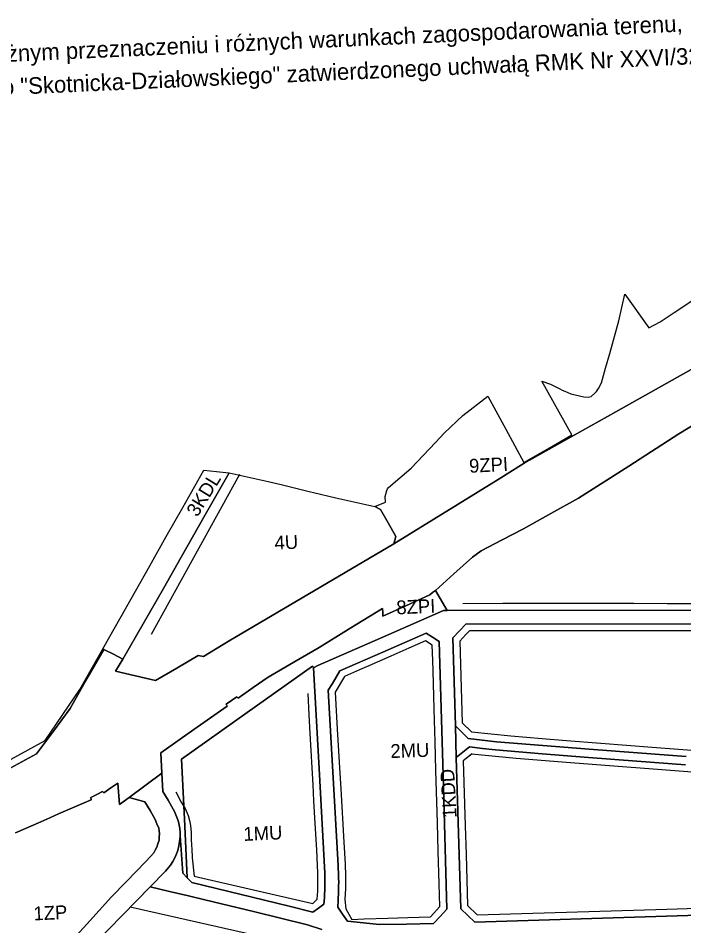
# Model space of a CAD drawing. Extents: x 7418021 to 7419743, y 5540231 to 5541685.
# Drawn here: x 7418764 to 7419247, y 5541026 to 5541685 of the extents above; entities that cross this region are included whole.
import ezdxf

# ---------------------------------------------------------------- set-up
doc = ezdxf.new("R2010")
doc.units = 0
for name, color, linetype in [('info', 7, 'Continuous'), ('linie_rozgraniczajace', 7, 'Continuous'), ('linie_zabudowy_nieprzekraczalne', 7, 'Continuous'), ('oznaczenia_przeznaczen', 7, 'Continuous')]:
    doc.layers.add(name, color=color, linetype=linetype)

msp = doc.modelspace()

# ---------------------------------------------------------------- linework, layer by layer
at = {"layer": 'linie_rozgraniczajace'}
for points in [[(7419264.06, 5541436.17), (7419197.72, 5541398.92), (7419131.37, 5541361.67), (7419131.05, 5541362.12), (7419148.44, 5541372.18), (7419165.84, 5541382.25), (7419144.09, 5541421.08), (7419150.41, 5541418.88), (7419157.19, 5541415.49), (7419158.97, 5541414.65), (7419160.74, 5541413.8), (7419165.14, 5541412.08), (7419174.5, 5541409.72), (7419177.8, 5541409.47), (7419180.02, 5541409.94), (7419182.83, 5541412.7), (7419183.74, 5541413.6), (7419185.3, 5541415.8), (7419187.43, 5541419.95), (7419190.41, 5541430.57), (7419193.39, 5541441.19), (7419199.93, 5541464.97), (7419204.41, 5541484.28), (7419221.63, 5541459.9), (7419229.97, 5541464.16), (7419240, 5541470.9), (7419241.95, 5541472.21), (7419268.64, 5541490.14)], [(7418742.75, 5541131.91), (7418777.69, 5541150.66), (7418789.83, 5541167.12), (7418801.97, 5541183.59), (7418814.18, 5541205.07), (7418826.39, 5541226.55), (7418833.35, 5541222.96), (7418840.31, 5541219.37), (7418834.89, 5541210.65), (7418849.45, 5541207.26), (7418864.02, 5541203.87), (7418879.49, 5541213.02), (7418894.95, 5541222.16), (7418898.76, 5541221.27), (7418917.39, 5541232.64), (7419036.88, 5541303.16), (7419112.45, 5541349.78), (7419131.37, 5541361.67), (7419197.72, 5541398.92), (7419264.06, 5541436.17)], [(7419305.93, 5541420.97), (7419243.56, 5541382.86), (7419207.12, 5541359.52), (7419170.68, 5541336.19), (7419150.78, 5541325.05), (7419130.88, 5541313.92), (7419115.45, 5541305.98), (7419100.02, 5541298.04), (7419093.87, 5541293.42), (7419080.42, 5541281.38), (7419066.97, 5541269.34), (7419064.9, 5541267.73), (7419062.83, 5541266.12), (7419045.87, 5541258.36), (7419028.91, 5541250.61), (7419028.69, 5541253.4)], [(7419298.53, 5541254.95), (7419075.49, 5541254.87), (7419066.97, 5541269.34), (7419080.42, 5541281.38), (7419093.87, 5541293.42), (7419100.02, 5541298.04), (7419115.45, 5541305.98), (7419130.88, 5541313.92), (7419150.78, 5541325.05), (7419170.68, 5541336.19), (7419207.12, 5541359.52), (7419243.56, 5541382.86), (7419305.93, 5541420.97)], [(7419028.69, 5541253.4), (7419028.48, 5541256.19), (7419005.52, 5541242.1), (7418982.57, 5541228), (7418964.15, 5541217.25), (7418945.74, 5541206.49), (7418934.77, 5541198.83), (7418923.8, 5541191.17), (7418923.34, 5541191.68), (7418922.89, 5541192.2), (7418918.99, 5541189.47), (7418915.08, 5541186.75), (7418916, 5541185.36), (7418891.84, 5541168.43), (7418867.68, 5541151.49), (7418868.53, 5541136.69), (7418844.8, 5541119.15), (7418837.76, 5541113.94), (7418836.72, 5541129.55), (7418831.57, 5541126.04), (7418826.43, 5541122.53), (7418825.48, 5541123.51), (7418821.25, 5541121.25), (7418817.02, 5541119), (7418817.29, 5541117.38), (7418805.4, 5541112.33), (7418793.51, 5541107.27), (7418787.18, 5541104.33), (7418780.85, 5541101.4), (7418762.43, 5541093.5)], [(7418883.64, 5541064.17), (7418886.94, 5541060.75), (7418890.24, 5541057.32), (7418960.86, 5541040.15), (7418978.13, 5541035.89), (7418982.1, 5541038.8), (7418986.08, 5541041.71), (7418986.41, 5541046.14), (7418986.58, 5541049.33), (7418986.64, 5541050.96), (7418986.75, 5541054.72), (7418986.79, 5541057.9), (7418986.77, 5541060.93), (7418986.7, 5541064.21), (7418982.59, 5541140.19), (7418978.58, 5541213.14), (7418981.57, 5541214.72), (7419027.22, 5541234.79), (7419072.87, 5541254.85), (7419075.49, 5541254.87), (7419298.53, 5541254.95)], [(7419295.55, 5541244.94), (7419089.24, 5541244.96), (7419084.38, 5541239.95), (7419079.53, 5541234.94), (7419081.4, 5541171.04), (7419082.07, 5541148.05), (7419085.29, 5541038.29), (7419090.43, 5541033.48), (7419095.57, 5541028.67), (7419234.58, 5541032.97), (7419373.59, 5541037.27)], [(7419248.73, 5541148.79), (7419213.55, 5541151.46), (7419178.38, 5541154.14), (7419144.78, 5541156.83), (7419111.18, 5541159.53), (7419100.94, 5541160.69), (7419090.71, 5541161.86), (7419081.4, 5541171.04), (7419079.53, 5541234.94), (7419084.38, 5541239.95), (7419089.24, 5541244.96), (7419295.55, 5541244.94)], [(7419248.28, 5541142.8), (7419213.1, 5541145.48), (7419177.92, 5541148.15), (7419144.26, 5541150.85), (7419110.6, 5541153.55), (7419101.15, 5541154.63), (7419091.71, 5541155.7), (7419086.89, 5541151.88), (7419082.07, 5541148.05), (7419081.4, 5541171.04), (7419090.71, 5541161.86), (7419100.94, 5541160.69), (7419111.18, 5541159.53), (7419144.78, 5541156.83), (7419178.38, 5541154.14), (7419213.55, 5541151.46), (7419248.73, 5541148.79)], [(7419373.59, 5541037.27), (7419234.58, 5541032.97), (7419095.57, 5541028.67), (7419090.43, 5541033.48), (7419085.29, 5541038.29), (7419082.07, 5541148.05), (7419086.89, 5541151.88), (7419091.71, 5541155.7), (7419101.15, 5541154.63), (7419110.6, 5541153.55), (7419144.26, 5541150.85), (7419177.92, 5541148.15), (7419213.1, 5541145.48), (7419248.28, 5541142.8)], [(7418796.31, 5541007.56), (7418814.14, 5541027.22), (7418831.98, 5541046.89), (7418842.72, 5541057.93), (7418856.93, 5541072.55), (7418860.41, 5541076.13), (7418862.63, 5541078.85), (7418863.79, 5541080.89), (7418864.94, 5541082.93), (7418865.7, 5541085.53), (7418866.46, 5541088.14), (7418866.6, 5541090.46), (7418866.75, 5541092.78), (7418866.49, 5541094.75), (7418866.24, 5541096.71), (7418864.99, 5541099.89), (7418863.75, 5541103.08), (7418860.02, 5541109.52), (7418856.29, 5541115.97), (7418844.8, 5541119.15), (7418868.53, 5541136.69)], [(7418868.53, 5541136.69), (7418869.27, 5541123.48), (7418873, 5541117.04), (7418876.73, 5541110.59), (7418877.71, 5541108.79), (7418878.23, 5541107.67), (7418878.76, 5541106.55), (7418879.71, 5541104.09), (7418880.12, 5541102.76), (7418880.52, 5541101.43), (7418880.81, 5541100.19), (7418881.29, 5541097.71), (7418881.49, 5541096.47), (7418881.74, 5541093.53), (7418881.7, 5541091.2), (7418881.66, 5541088.87), (7418880.89, 5541083.96), (7418880.05, 5541080.63), (7418879.17, 5541078.13), (7418878.72, 5541076.99), (7418877.66, 5541074.72), (7418876.43, 5541072.52), (7418874.69, 5541069.87), (7418871.17, 5541065.67), (7418860.04, 5541054.22), (7418820.04, 5541013.07)], [(7418762.43, 5541093.5), (7418780.85, 5541101.4), (7418787.18, 5541104.33), (7418793.51, 5541107.27), (7418805.4, 5541112.33), (7418817.29, 5541117.38), (7418817.02, 5541119), (7418821.25, 5541121.25), (7418825.48, 5541123.51), (7418826.43, 5541122.53), (7418831.57, 5541126.04), (7418836.72, 5541129.55), (7418837.76, 5541113.94), (7418844.8, 5541119.15), (7418856.29, 5541115.97), (7418860.02, 5541109.52), (7418863.75, 5541103.08), (7418864.99, 5541099.89), (7418866.24, 5541096.71), (7418866.49, 5541094.75), (7418866.75, 5541092.78), (7418866.6, 5541090.46), (7418866.46, 5541088.14), (7418865.7, 5541085.53), (7418864.94, 5541082.93), (7418863.79, 5541080.89), (7418862.63, 5541078.85), (7418860.41, 5541076.13), (7418856.93, 5541072.55), (7418842.72, 5541057.93), (7418831.98, 5541046.89), (7418814.14, 5541027.22), (7418796.31, 5541007.56)], [(7418984.55, 5541023.35), (7418974.12, 5541026.58), (7418935.01, 5541036.21), (7418899.75, 5541044.79), (7418887.93, 5541047.59), (7418873.98, 5541050.9), (7418860.04, 5541054.22), (7418871.17, 5541065.67), (7418874.69, 5541069.87), (7418876.43, 5541072.52), (7418877.66, 5541074.72), (7418878.72, 5541076.99), (7418879.17, 5541078.13), (7418880.05, 5541080.63), (7418880.89, 5541083.96), (7418881.66, 5541088.87), (7418881.7, 5541091.2), (7418882.67, 5541077.69), (7418883.64, 5541064.17)], [(7418820.04, 5541013.07), (7418860.04, 5541054.22), (7418873.98, 5541050.9), (7418887.93, 5541047.59), (7418899.75, 5541044.79), (7418935.01, 5541036.21), (7418974.12, 5541026.58), (7418984.55, 5541023.35)]]:
    msp.add_lwpolyline(points, dxfattribs=at)
for points in [[(7419032.28, 5541342.94), (7419032.82, 5541344.03), (7419041.06, 5541351.03), (7419049.3, 5541358.04), (7419058.15, 5541367.33), (7419067, 5541376.61), (7419073.63, 5541383.76), (7419086.75, 5541396.36), (7419105.07, 5541410.34), (7419118.06, 5541386.23), (7419131.05, 5541362.12), (7419131.37, 5541361.67), (7419112.45, 5541349.78), (7419036.88, 5541303.16), (7419036.9, 5541303.24), (7419038.24, 5541308.51), (7419032.63, 5541318.27), (7419027.03, 5541328.04), (7419022.91, 5541330.31), (7419030.73, 5541333.29), (7419030.49, 5541337.45), (7419031.74, 5541341.84)], [(7418838.98, 5541250.29), (7418859.7, 5541287.19), (7418871.7, 5541308.37), (7418883.77, 5541329.49), (7418899.07, 5541356.65), (7418908.09, 5541355.71), (7418917.11, 5541354.76), (7418917.38, 5541354.7), (7418899.86, 5541324.08), (7418882.62, 5541293.4), (7418869.84, 5541270.72), (7418840.31, 5541219.37), (7418833.35, 5541222.96), (7418826.39, 5541226.55), (7418825.81, 5541226.83)], [(7418864.02, 5541203.87), (7418849.45, 5541207.26), (7418834.89, 5541210.65), (7418840.31, 5541219.37), (7418869.84, 5541270.72), (7418882.62, 5541293.4), (7418899.86, 5541324.08), (7418917.38, 5541354.7), (7418945.56, 5541348.36), (7418954.98, 5541346.24), (7418976.25, 5541340.91), (7418978.41, 5541340.37), (7418994.78, 5541336.41), (7419022.91, 5541330.31), (7419027.03, 5541328.04), (7419032.63, 5541318.27), (7419038.24, 5541308.51), (7419036.9, 5541303.24), (7419036.88, 5541303.16), (7418917.39, 5541232.64), (7418898.76, 5541221.27), (7418894.95, 5541222.16), (7418879.49, 5541213.02)], [(7419066.97, 5541269.34), (7419075.49, 5541254.87), (7419072.87, 5541254.85), (7419027.22, 5541234.79), (7418981.57, 5541214.72), (7418978.58, 5541213.14), (7418978.23, 5541213.76), (7418977.89, 5541214.36), (7418930.31, 5541180.62), (7418882.73, 5541146.87), (7418884.97, 5541103.67), (7418886.94, 5541060.75), (7418883.64, 5541064.17), (7418882.67, 5541077.69), (7418881.7, 5541091.2), (7418881.74, 5541093.53), (7418881.49, 5541096.47), (7418881.29, 5541097.71), (7418880.81, 5541100.19), (7418880.52, 5541101.43), (7418880.12, 5541102.76), (7418879.71, 5541104.09), (7418878.76, 5541106.55), (7418878.23, 5541107.67), (7418877.71, 5541108.79), (7418876.73, 5541110.59), (7418873, 5541117.04), (7418869.27, 5541123.48), (7418868.53, 5541136.69), (7418867.68, 5541151.49), (7418891.84, 5541168.43), (7418916, 5541185.36), (7418915.08, 5541186.75), (7418918.99, 5541189.47), (7418922.89, 5541192.2), (7418923.34, 5541191.68), (7418923.8, 5541191.17), (7418934.77, 5541198.83), (7418945.74, 5541206.49), (7418964.15, 5541217.25), (7418982.57, 5541228), (7419005.52, 5541242.1), (7419028.48, 5541256.19), (7419028.69, 5541253.4), (7419028.91, 5541250.61), (7419045.87, 5541258.36), (7419062.83, 5541266.12), (7419064.9, 5541267.73)], [(7419069.6, 5541232.37), (7419064.88, 5541235.35), (7419060.15, 5541238.34), (7419028.89, 5541224.6), (7418997.63, 5541210.85), (7418992.3, 5541201.84), (7418989.06, 5541196.85), (7418992.77, 5541133.22), (7418996.48, 5541069.6), (7418996.75, 5541062.15), (7418996.77, 5541060.02), (7418996.79, 5541057.89), (7418996.73, 5541054.77), (7418996.68, 5541051.65), (7418996.55, 5541048.96), (7418996.43, 5541046.26), (7418996.29, 5541044.27), (7418996.11, 5541039.56), (7418999.62, 5541034.48), (7419003.13, 5541029.39), (7419014.68, 5541028.14), (7419026.23, 5541026.88), (7419045.91, 5541027.22), (7419065.59, 5541027.56), (7419070.44, 5541032.74), (7419075.29, 5541037.92), (7419072.45, 5541135.14)], [(7419069.6, 5541232.37), (7419072.45, 5541135.14), (7419075.29, 5541037.92), (7419070.44, 5541032.74), (7419065.59, 5541027.56), (7419045.91, 5541027.22), (7419026.23, 5541026.88), (7419014.68, 5541028.14), (7419003.13, 5541029.39), (7418999.62, 5541034.48), (7418996.11, 5541039.56), (7418996.29, 5541044.27), (7418996.43, 5541046.26), (7418996.55, 5541048.96), (7418996.68, 5541051.65), (7418996.73, 5541054.77), (7418996.79, 5541057.89), (7418996.77, 5541060.02), (7418996.75, 5541062.15), (7418996.48, 5541069.6), (7418992.77, 5541133.22), (7418989.06, 5541196.85), (7418992.3, 5541201.84), (7418997.63, 5541210.85), (7419028.89, 5541224.6), (7419060.15, 5541238.34), (7419064.88, 5541235.35)], [(7418826.39, 5541226.55), (7418814.18, 5541205.07), (7418801.97, 5541183.59), (7418789.83, 5541167.12), (7418777.69, 5541150.66), (7418742.75, 5541131.91), (7418712.48, 5541116.29), (7418685.89, 5541102.62), (7418659.3, 5541088.95), (7418633.99, 5541078.77), (7418529.23, 5541035.2), (7418449.78, 5541001.82), (7418444.4, 5541004.3), (7418520.87, 5541036.04), (7418619.89, 5541077.13), (7418704.01, 5541117.02), (7418743.95, 5541138.74), (7418783.9, 5541160.46), (7418808.95, 5541197.4), (7418825.59, 5541226.44), (7418825.81, 5541226.83)], [(7418886.94, 5541060.75), (7418884.97, 5541103.67), (7418882.73, 5541146.87), (7418930.31, 5541180.62), (7418977.89, 5541214.36), (7418978.23, 5541213.76), (7418978.58, 5541213.14), (7418982.59, 5541140.19), (7418986.7, 5541064.21), (7418986.77, 5541060.93), (7418986.79, 5541057.9), (7418986.75, 5541054.72), (7418986.64, 5541050.96), (7418986.58, 5541049.33), (7418986.41, 5541046.14), (7418986.08, 5541041.71), (7418982.1, 5541038.8), (7418978.13, 5541035.89), (7418960.86, 5541040.15), (7418890.24, 5541057.32)]]:
    msp.add_lwpolyline(points, close=True, dxfattribs=at)
at = {"layer": 'linie_zabudowy_nieprzekraczalne'}
for points in [[(7418924.88, 5541353.49), (7418860.86, 5541237.41)], [(7419086.75, 5541259.89), (7419115.95, 5541259.97)], [(7419115.95, 5541259.97), (7419136.8, 5541259.96)], [(7419136.8, 5541259.96), (7419159.88, 5541259.96)], [(7419159.88, 5541259.96), (7419184.74, 5541259.96)], [(7419184.74, 5541259.96), (7419210.9, 5541259.96)], [(7419210.9, 5541259.96), (7419235.07, 5541259.95)], [(7419235.07, 5541259.95), (7419266.19, 5541259.95)], [(7419091.73, 5541239.96), (7419088.94, 5541237.23)], [(7419116.54, 5541239.96), (7419091.73, 5541239.96)], [(7419131.96, 5541239.95), (7419116.54, 5541239.96)], [(7419158.04, 5541239.95), (7419131.96, 5541239.95)], [(7419201.16, 5541239.95), (7419158.04, 5541239.95)], [(7419217.3, 5541239.95), (7419201.16, 5541239.95)], [(7419242.13, 5541239.95), (7419217.3, 5541239.95)], [(7419277.44, 5541239.94), (7419242.13, 5541239.95)], [(7419059.73, 5541232.69), (7419047.65, 5541227.38)], [(7419064.68, 5541229.56), (7419059.73, 5541232.69)], [(7419088.94, 5541237.23), (7419084.77, 5541232.51)], [(7419084.77, 5541232.51), (7419085.35, 5541207.02)], [(7419047.65, 5541227.38), (7419034.54, 5541221.62)], [(7419065, 5541218.56), (7419064.68, 5541229.56)], [(7419034.54, 5541221.62), (7419018.72, 5541214.67)], [(7419065.22, 5541211.05), (7419065, 5541218.56)], [(7419011.9, 5541211.67), (7419001.08, 5541206.91)], [(7419018.72, 5541214.67), (7419011.9, 5541211.67)], [(7419001.08, 5541206.91), (7418994.14, 5541195.58)], [(7419065.77, 5541192.35), (7419065.22, 5541211.05)], [(7419085.35, 5541207.02), (7419086.34, 5541173.19)], [(7418975.45, 5541179.09), (7418974.6, 5541194.55)], [(7418994.14, 5541195.58), (7418995.71, 5541168.69)], [(7419066.28, 5541174.86), (7419065.77, 5541192.35)], [(7418976.2, 5541165.49), (7418975.45, 5541179.09)], [(7419066.73, 5541159.49), (7419066.28, 5541174.86)], [(7419086.34, 5541173.19), (7419093, 5541166.63)], [(7418978.24, 5541128.28), (7418976.2, 5541165.49)], [(7418995.71, 5541168.69), (7418997.58, 5541136.61)], [(7419093, 5541166.63), (7419121.6, 5541163.71)], [(7419067.35, 5541138.53), (7419066.73, 5541159.49)], [(7419121.6, 5541163.71), (7419144.37, 5541161.88)], [(7419144.37, 5541161.88), (7419162.1, 5541160.46)], [(7419162.1, 5541160.46), (7419186.84, 5541158.51)], [(7419186.84, 5541158.51), (7419224.22, 5541155.67)], [(7419224.22, 5541155.67), (7419246.39, 5541153.98)], [(7419246.39, 5541153.98), (7419273.49, 5541151.98)], [(7419093.58, 5541150.8), (7419087.15, 5541145.7)], [(7419093.2, 5541150.5), (7419087.15, 5541145.7)], [(7419087.15, 5541145.7), (7419088.53, 5541098.52)], [(7419125.46, 5541147.35), (7419093.2, 5541150.5)], [(7419165.02, 5541144.17), (7419125.46, 5541147.35)], [(7419347.74, 5541130.08), (7419165.02, 5541144.17)], [(7418997.58, 5541136.61), (7418998.23, 5541125.45)], [(7419068.46, 5541100.64), (7419067.35, 5541138.53)], [(7418978.88, 5541116.59), (7418978.24, 5541128.28)], [(7418878.65, 5541123.25), (7418882.57, 5541115.71)], [(7418998.23, 5541125.45), (7419000.49, 5541086.69)], [(7418882.57, 5541115.71), (7418885.51, 5541111.01)], [(7418979.78, 5541100.19), (7418978.88, 5541116.59)], [(7418885.51, 5541111.01), (7418887.5, 5541105.98)], [(7418887.5, 5541105.98), (7418888.52, 5541102.37)], [(7418888.52, 5541102.37), (7418889.22, 5541098.81)], [(7418980.83, 5541081.17), (7418979.78, 5541100.19)], [(7419069.06, 5541080.02), (7419068.46, 5541100.64)], [(7418889.22, 5541098.81), (7418889.74, 5541093.65)], [(7418889.74, 5541093.65), (7418889.67, 5541089.13)], [(7419088.53, 5541098.52), (7419089.14, 5541077.64)], [(7418889.67, 5541089.13), (7418890.13, 5541084.19)], [(7419000.49, 5541086.69), (7419001.43, 5541070.64)], [(7418890.13, 5541084.19), (7418890.23, 5541081.73)], [(7418890.23, 5541081.73), (7418890.42, 5541075.17)], [(7418981.46, 5541069.66), (7418980.83, 5541081.17)], [(7419069.75, 5541056.44), (7419069.06, 5541080.02)], [(7418890.42, 5541075.17), (7418891.95, 5541062.06)], [(7419089.14, 5541077.64), (7419090.22, 5541040.79)], [(7418981.69, 5541064.42), (7418981.46, 5541069.66)], [(7419001.43, 5541070.64), (7419001.76, 5541062.1)], [(7418891.95, 5541062.06), (7418978.04, 5541042.13)], [(7418981.78, 5541059.87), (7418981.69, 5541064.42)], [(7418981.77, 5541055.83), (7418981.78, 5541059.87)], [(7419001.76, 5541062.1), (7419001.71, 5541053.09)], [(7418981.65, 5541051.11), (7418981.77, 5541055.83)], [(7419070.24, 5541039.84), (7419069.75, 5541056.44)], [(7418981.23, 5541045.22), (7418981.65, 5541051.11)], [(7419001.71, 5541053.09), (7419001.36, 5541044.98)], [(7418978.04, 5541042.13), (7418981.23, 5541045.22)], [(7419001.36, 5541044.98), (7419002.07, 5541038.17)], [(7419090.22, 5541040.79), (7419097.21, 5541033.98)], [(7418997.35, 5541005.22), (7418845.61, 5541039.37)], [(7419002.07, 5541038.17), (7419006.4, 5541030.56)], [(7419063.36, 5541032.49), (7419070.24, 5541039.84)], [(7419097.21, 5541033.98), (7419234.68, 5541038.02)], [(7419234.68, 5541038.02), (7419293.98, 5541039.83)], [(7419006.4, 5541030.56), (7419015.33, 5541030.88)], [(7419015.33, 5541030.88), (7419032.45, 5541031.47)], [(7419032.45, 5541031.47), (7419046.94, 5541031.95)], [(7419046.94, 5541031.95), (7419063.36, 5541032.49)]]:
    msp.add_lwpolyline(points, dxfattribs=at)

# ---------------------------------------------------------------- texts
at = {"layer": 'info'}
for s, p in [('Materiał pomocniczy zawierający linie rozgraniczające teren o różnym przeznaczeniu i różnych warunkach zagospodarowania terenu, ', (7418299.29, 5541632.34)), ('opracowane w skali 1:2000 pochodzące z Miejscowego Planu Zagospodarowania Przestrzennego "Skotnicka-Działowskiego" zatwierdzonego uchwałą RMK Nr XXVI/326/07 z dnia 7 listopada 2007r.', (7418064.81, 5541597.78))]:
    msp.add_text(s, height=12, rotation=2.57107, dxfattribs=at).set_placement(p)
at = {"layer": 'oznaczenia_przeznaczen'}
for s, rotation, p in [('9ZPI', 3.14286, (7419091.66, 5541354.62)), ('3KDL', 58.38974, (7418894.29, 5541322.04)), ('4U', 2.57107, (7418950.49, 5541298.86)), ('8ZPI', 2.66896, (7419038.85, 5541251.9)), ('2MU', 1.97674, (7419034.48, 5541147.66)), ('1KDD', 93.0901, (7419082.38, 5541104.43)), ('1MU', 2.57107, (7418927.92, 5541087.5)), ('1ZP', 2.57107, (7418775.66, 5541029.83))]:
    msp.add_text(s, height=10, rotation=rotation, dxfattribs=at).set_placement(p)

doc.saveas('drawing.dxf')
